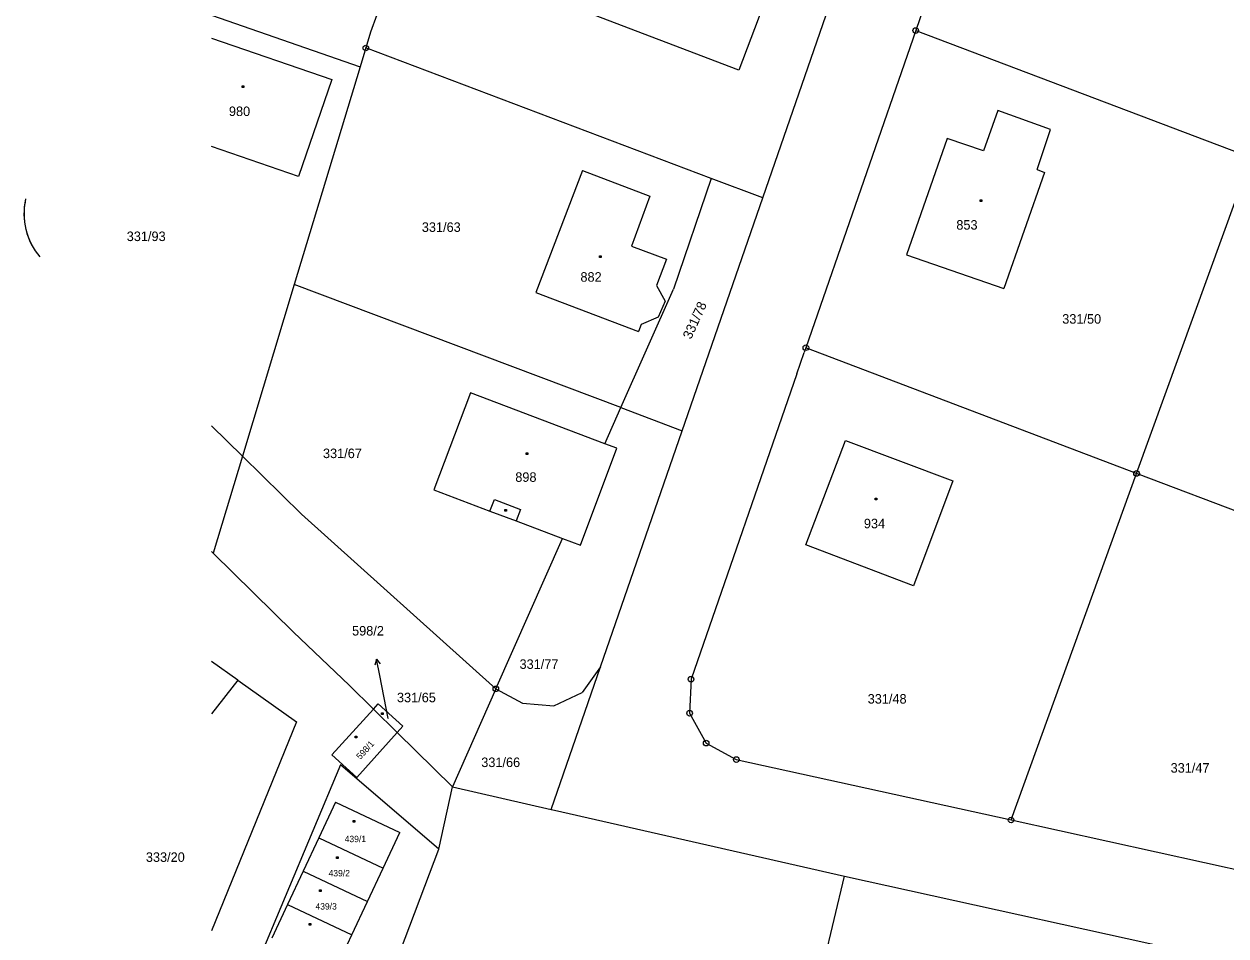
# Model space of a CAD drawing. Extents: x -770973 to -770265, y -1049936 to -1049427.
# Drawn here: x -770972.9 to -770865.5, y -1049866.1 to -1049784.7 of the extents above; entities that cross this region are included whole.
import ezdxf

# ---------------------------------------------------------------- set-up
doc = ezdxf.new("R2010")
doc.units = 0
for name, color, linetype in [('Vrstva 1', 7, 'Continuous'), ('Vrstva 13', 7, 'Continuous'), ('Vrstva 14', 7, 'Continuous'), ('Vrstva 15', 7, 'Continuous'), ('Vrstva 16', 7, 'Continuous'), ('Vrstva 2', 7, 'Continuous'), ('Vrstva 25', 7, 'Continuous'), ('Vrstva 28', 7, 'Continuous'), ('Vrstva 30', 7, 'Continuous')]:
    doc.layers.add(name, color=color, linetype=linetype)

msp = doc.modelspace()

# ---------------------------------------------------------------- linework, layer by layer
at = {"layer": 'Vrstva 1'}
for p, q in [((-770881.77, -1049752.1), (-770893.23, -1049785.23)), ((-770934.9, -1049766.08), (-770941.92, -1049785.38)), ((-770906.89, -1049800.18), (-770899.72, -1049779.45)), ((-770909.04, -1049788.76), (-770923.25, -1049783.35)), ((-770906.89, -1049783.11), (-770909.04, -1049788.76)), ((-770956.13, -1049783.87), (-770942.86, -1049788.47)), ((-770941.92, -1049785.38), (-770942.35, -1049786.79)), ((-770893.23, -1049785.23), (-770903.04, -1049813.57)), ((-770893.23, -1049785.23), (-770863.27, -1049796.58)), ((-770956.13, -1049785.92), (-770945.4, -1049789.62)), ((-770942.35, -1049786.79), (-770942.86, -1049788.47)), ((-770911.49, -1049798.44), (-770942.35, -1049786.79)), ((-770942.86, -1049788.47), (-770948.74, -1049807.91)), ((-770945.4, -1049789.62), (-770948.38, -1049798.26)), ((-770885.9, -1049792.39), (-770887.17, -1049795.98)), ((-770881.18, -1049794.06), (-770885.9, -1049792.39)), ((-770882.39, -1049797.66), (-770881.18, -1049794.06)), ((-770890.43, -1049794.87), (-770894.04, -1049805.27)), ((-770887.17, -1049795.98), (-770890.43, -1049794.87)), ((-770948.38, -1049798.26), (-770956.13, -1049795.6)), ((-770873.5, -1049824.8), (-770863.27, -1049796.58)), ((-770922.99, -1049797.73), (-770927.15, -1049808.63)), ((-770922.99, -1049797.73), (-770916.97, -1049800.02)), ((-770911.49, -1049798.44), (-770914.88, -1049808.35)), ((-770906.89, -1049800.18), (-770911.49, -1049798.44)), ((-770881.72, -1049797.9), (-770885.35, -1049808.28)), ((-770882.39, -1049797.66), (-770881.72, -1049797.9)), ((-770916.97, -1049800.02), (-770918.61, -1049804.51)), ((-770914.09, -1049820.99), (-770906.89, -1049800.18)), ((-770918.61, -1049804.51), (-770915.49, -1049805.65)), ((-770915.49, -1049805.65), (-770916.38, -1049808.01)), ((-770894.04, -1049805.27), (-770885.35, -1049808.28)), ((-770948.74, -1049807.91), (-770953.38, -1049823.25)), ((-770919.58, -1049818.92), (-770948.74, -1049807.91)), ((-770919.58, -1049818.92), (-770914.88, -1049808.35)), ((-770916.38, -1049808.01), (-770915.62, -1049809.4)), ((-770927.15, -1049808.63), (-770918, -1049812.13)), ((-770915.62, -1049809.4), (-770916.25, -1049810.83)), ((-770917.76, -1049811.48), (-770918, -1049812.13)), ((-770916.25, -1049810.83), (-770917.76, -1049811.48)), ((-770903.04, -1049813.57), (-770903.19, -1049813.99)), ((-770873.5, -1049824.8), (-770903.04, -1049813.57)), ((-770903.84, -1049815.89), (-770903.19, -1049813.99)), ((-770903.84, -1049815.89), (-770913.3, -1049843.18)), ((-770933.01, -1049817.61), (-770936.28, -1049826.27)), ((-770921.01, -1049822.14), (-770933.01, -1049817.61)), ((-770921.01, -1049822.14), (-770919.58, -1049818.92)), ((-770919.58, -1049818.92), (-770914.09, -1049820.99)), ((-770956.13, -1049820.55), (-770953.38, -1049823.25)), ((-770921.38, -1049842.08), (-770914.09, -1049820.99)), ((-770919.93, -1049822.55), (-770921.01, -1049822.14)), ((-770903.04, -1049831.18), (-770899.49, -1049821.86)), ((-770899.49, -1049821.86), (-770889.9, -1049825.47)), ((-770953.38, -1049823.25), (-770956, -1049831.91)), ((-770953.38, -1049823.25), (-770948.1, -1049828.45)), ((-770923.17, -1049831.21), (-770919.93, -1049822.55)), ((-770889.9, -1049825.47), (-770893.44, -1049834.83)), ((-770884.71, -1049855.76), (-770873.5, -1049824.8)), ((-770844.07, -1049835.99), (-770873.5, -1049824.8)), ((-770936.28, -1049826.27), (-770931.27, -1049828.17)), ((-770948.1, -1049828.45), (-770930.74, -1049844.04)), ((-770931.27, -1049828.17), (-770928.91, -1049829.04)), ((-770928.91, -1049829.04), (-770924.77, -1049830.61)), ((-770930.74, -1049844.04), (-770924.77, -1049830.61)), ((-770924.77, -1049830.61), (-770923.17, -1049831.21)), ((-770956, -1049831.91), (-770956.13, -1049831.78)), ((-770956, -1049831.91), (-770948.81, -1049838.97)), ((-770893.44, -1049834.83), (-770903.04, -1049831.18)), ((-770948.81, -1049838.97), (-770943.84, -1049843.72)), ((-770953.79, -1049843.27), (-770956.13, -1049841.61)), ((-770925.79, -1049854.81), (-770921.38, -1049842.08)), ((-770921.38, -1049842.08), (-770923.03, -1049844.38)), ((-770953.79, -1049843.27), (-770956.13, -1049846.29)), ((-770953.79, -1049843.27), (-770948.54, -1049846.99)), ((-770943.84, -1049843.72), (-770941.67, -1049845.86)), ((-770913.3, -1049843.18), (-770913.43, -1049846.22)), ((-770930.74, -1049844.04), (-770934.61, -1049852.79)), ((-770930.74, -1049844.04), (-770928.36, -1049845.33)), ((-770925.55, -1049845.56), (-770923.03, -1049844.38)), ((-770941.67, -1049845.86), (-770945.4, -1049849.94)), ((-770941.67, -1049845.86), (-770941.24, -1049845.39)), ((-770941.67, -1049845.86), (-770939.55, -1049847.94)), ((-770941.24, -1049845.39), (-770939.04, -1049847.37)), ((-770928.36, -1049845.33), (-770925.55, -1049845.56)), ((-770948.54, -1049846.99), (-770956.13, -1049865.66)), ((-770913.43, -1049846.22), (-770911.95, -1049848.89)), ((-770939.55, -1049847.94), (-770943.14, -1049851.96)), ((-770939.04, -1049847.37), (-770939.55, -1049847.94)), ((-770939.55, -1049847.94), (-770934.61, -1049852.79)), ((-770911.95, -1049848.89), (-770909.26, -1049850.36)), ((-770945.4, -1049849.94), (-770943.14, -1049851.96)), ((-770944.6, -1049850.84), (-770952.32, -1049869.22)), ((-770935.83, -1049858.36), (-770944.6, -1049850.84)), ((-770909.26, -1049850.36), (-770884.71, -1049855.76)), ((-770935.83, -1049858.36), (-770934.61, -1049852.79)), ((-770934.61, -1049852.79), (-770925.79, -1049854.81)), ((-770945.07, -1049854.18), (-770946.55, -1049857.35)), ((-770945.07, -1049854.18), (-770939.32, -1049856.88)), ((-770925.79, -1049854.81), (-770925.51, -1049854.88)), ((-770925.51, -1049854.88), (-770899.58, -1049860.79)), ((-770884.71, -1049855.76), (-770858.71, -1049861.47)), ((-770946.55, -1049857.35), (-770947.96, -1049860.34)), ((-770946.55, -1049857.35), (-770940.81, -1049860.05)), ((-770940.81, -1049860.05), (-770939.32, -1049856.88)), ((-770942.3, -1049875.44), (-770935.83, -1049858.36)), ((-770947.96, -1049860.34), (-770949.36, -1049863.32)), ((-770947.96, -1049860.34), (-770942.21, -1049863.04)), ((-770942.21, -1049863.04), (-770940.81, -1049860.05)), ((-770910.45, -1049906.19), (-770899.58, -1049860.79)), ((-770899.58, -1049860.79), (-770859.41, -1049869.62)), ((-770943.61, -1049866.02), (-770942.21, -1049863.04)), ((-770949.36, -1049863.32), (-770950.76, -1049866.31)), ((-770949.36, -1049863.32), (-770943.61, -1049866.02)), ((-770945.01, -1049869.01), (-770943.61, -1049866.02))]:
    msp.add_line(p, q, dxfattribs=at)
at = {"layer": 'Vrstva 13'}
msp.add_line((-770940.36, -1049846.7), (-770941.11, -1049842.85), dxfattribs=at)
at = {"layer": 'Vrstva 16'}
for p, q in [((-770941.4, -1049841.38), (-770941.55, -1049841.92)), ((-770941.11, -1049842.85), (-770941.4, -1049841.38)), ((-770941.4, -1049841.38), (-770941.06, -1049841.82))]:
    msp.add_line(p, q, dxfattribs=at)
at = {"layer": 'Vrstva 2'}
for p, q in [((-770931.27, -1049828.17), (-770930.87, -1049827.12)), ((-770930.87, -1049827.12), (-770928.52, -1049828.02)), ((-770928.52, -1049828.02), (-770928.91, -1049829.04))]:
    msp.add_line(p, q, dxfattribs=at)
at = {"layer": 'Vrstva 25'}
for p, q in [((-770953.39, -1049790.18), (-770953.24, -1049790.18)), ((-770953.39, -1049790.33), (-770953.39, -1049790.18)), ((-770953.24, -1049790.33), (-770953.39, -1049790.33)), ((-770953.24, -1049790.18), (-770953.24, -1049790.33)), ((-770887.48, -1049800.36), (-770887.33, -1049800.36)), ((-770887.48, -1049800.51), (-770887.48, -1049800.36)), ((-770887.33, -1049800.51), (-770887.48, -1049800.51)), ((-770887.33, -1049800.36), (-770887.33, -1049800.51)), ((-770921.49, -1049805.37), (-770921.34, -1049805.37)), ((-770921.49, -1049805.52), (-770921.49, -1049805.37)), ((-770921.34, -1049805.52), (-770921.49, -1049805.52)), ((-770921.34, -1049805.37), (-770921.34, -1049805.52)), ((-770928.03, -1049822.95), (-770927.88, -1049822.95)), ((-770928.03, -1049823.1), (-770928.03, -1049822.95)), ((-770927.88, -1049823.1), (-770928.03, -1049823.1)), ((-770927.88, -1049822.95), (-770927.88, -1049823.1)), ((-770896.85, -1049827.01), (-770896.7, -1049827.01)), ((-770896.85, -1049827.16), (-770896.85, -1049827.01)), ((-770896.7, -1049827.16), (-770896.85, -1049827.16)), ((-770896.7, -1049827.01), (-770896.7, -1049827.16)), ((-770929.92, -1049828.01), (-770929.77, -1049828.01)), ((-770929.92, -1049828.16), (-770929.92, -1049828.01)), ((-770929.77, -1049828.16), (-770929.92, -1049828.16)), ((-770929.77, -1049828.01), (-770929.77, -1049828.16)), ((-770940.94, -1049846.19), (-770940.79, -1049846.19)), ((-770940.94, -1049846.34), (-770940.94, -1049846.19)), ((-770940.79, -1049846.34), (-770940.94, -1049846.34)), ((-770940.79, -1049846.19), (-770940.79, -1049846.34)), ((-770943.3, -1049848.28), (-770943.15, -1049848.28)), ((-770943.3, -1049848.43), (-770943.3, -1049848.28)), ((-770943.15, -1049848.43), (-770943.3, -1049848.43)), ((-770943.15, -1049848.28), (-770943.15, -1049848.43)), ((-770943.47, -1049855.8), (-770943.32, -1049855.8)), ((-770943.47, -1049855.95), (-770943.47, -1049855.8)), ((-770943.32, -1049855.95), (-770943.47, -1049855.95)), ((-770943.32, -1049855.8), (-770943.32, -1049855.95)), ((-770944.98, -1049859.04), (-770944.83, -1049859.04)), ((-770944.98, -1049859.19), (-770944.98, -1049859.04)), ((-770944.83, -1049859.19), (-770944.98, -1049859.19)), ((-770944.83, -1049859.04), (-770944.83, -1049859.19)), ((-770946.49, -1049861.99), (-770946.34, -1049861.99)), ((-770946.49, -1049862.14), (-770946.49, -1049861.99)), ((-770946.34, -1049861.99), (-770946.34, -1049862.14)), ((-770946.34, -1049862.14), (-770946.49, -1049862.14)), ((-770947.42, -1049865.01), (-770947.27, -1049865.01)), ((-770947.42, -1049865.16), (-770947.42, -1049865.01)), ((-770947.27, -1049865.16), (-770947.42, -1049865.16)), ((-770947.27, -1049865.01), (-770947.27, -1049865.16))]:
    msp.add_line(p, q, dxfattribs=at)
at = {"layer": 'Vrstva 28'}
for centre, radius in [((-770893.23, -1049785.23), 0.25), ((-770893.23, -1049785.23), 0.005), ((-770942.35, -1049786.79), 0.25), ((-770942.35, -1049786.79), 0.005), ((-770903.04, -1049813.57), 0.25), ((-770903.04, -1049813.57), 0.005), ((-770873.5, -1049824.8), 0.25), ((-770873.5, -1049824.8), 0.005), ((-770930.74, -1049844.04), 0.25), ((-770913.3, -1049843.18), 0.25), ((-770913.3, -1049843.18), 0.005), ((-770930.74, -1049844.04), 0.005), ((-770913.43, -1049846.22), 0.25), ((-770913.43, -1049846.22), 0.005), ((-770911.95, -1049848.89), 0.25), ((-770911.95, -1049848.89), 0.005), ((-770909.26, -1049850.36), 0.25), ((-770909.26, -1049850.36), 0.005), ((-770884.71, -1049855.76), 0.25), ((-770884.71, -1049855.76), 0.005)]:
    msp.add_circle(centre, radius, dxfattribs=at)
at = {"layer": 'Vrstva 30'}
for centre, radius, start, end in [((-770966.89, -1049801.58), 6, 167.465, 220.295), ((-770966.97, -1049801.57), 5.91, 167.4091, 189.5627), ((-770966.94, -1049801.61), 5.94, 193.2466, 220.4344)]:
    msp.add_arc(centre, radius, start, end, dxfattribs=at)

# ---------------------------------------------------------------- texts
at = {"layer": 'Vrstva 14'}
for s, p in [('331/63', (-770937.35, -1049803.22)), ('331/93', (-770963.71, -1049804.04)), ('331/50', (-770880.14, -1049811.42)), ('331/67', (-770946.18, -1049823.43)), ('331/77', (-770928.62, -1049842.26)), ('331/65', (-770939.57, -1049845.24)), ('331/48', (-770897.52, -1049845.36)), ('331/66', (-770932.04, -1049851.03)), ('331/47', (-770870.46, -1049851.53)), ('333/20', (-770962, -1049859.5))]:
    msp.add_text(s, height=0.85, dxfattribs=at).set_placement(p)
msp.add_text('331/78', height=0.85, rotation=65.7112, dxfattribs=at).set_placement((-770913.3, -1049812.87))
at = {"layer": 'Vrstva 15'}
for s, height, p in [('980', 0.85, (-770954.58, -1049792.87)), ('853', 0.85, (-770889.6, -1049803.02)), ('882', 0.85, (-770923.18, -1049807.67)), ('898', 0.85, (-770929, -1049825.55)), ('934', 0.85, (-770897.86, -1049829.7)), ('598/2', 0.05, (-770940.46, -1049846.7)), ('439/1', 0.57, (-770944.24, -1049857.74)), ('439/2', 0.57, (-770945.68, -1049860.8)), ('439/3', 0.57, (-770946.85, -1049863.76))]:
    msp.add_text(s, height=height, dxfattribs=at).set_placement(p)
msp.add_text('598/1', height=0.57, rotation=47.5562, dxfattribs=at).set_placement((-770942.84, -1049850.4))
at = {"layer": 'Vrstva 16'}
msp.add_text('598/2', height=0.85, dxfattribs=at).set_placement((-770943.58, -1049839.28))

doc.saveas('drawing.dxf')
